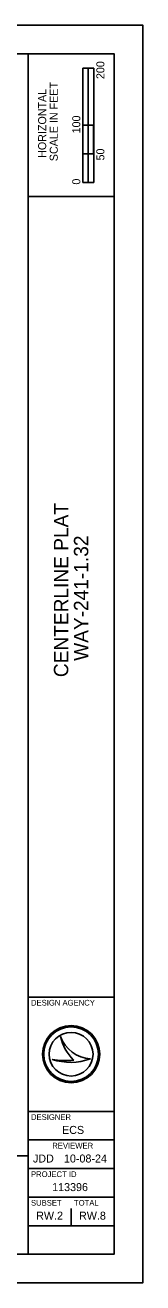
# Model space of a CAD drawing. Extents: x 2183298 to 2188248, y 369076 to 371276.
# Drawn here: x 2186493 to 2186698, y 369076 to 371276 of the extents above; entities that cross this region are included whole.
import ezdxf

# ---------------------------------------------------------------- set-up
doc = ezdxf.new("R2010")
doc.units = 0
for name, color, linetype in [('RD_X_RR_Cells', 7, 'Continuous'), ('SV_P_Mon_Cells_Set', 7, 'Continuous'), ('SV_X_Mon_Cells_Found', 7, 'Continuous'), ('SV_X_Shot_Marker', 7, 'Continuous')]:
    doc.layers.add(name, color=color, linetype=linetype)

msp = doc.modelspace()

# ---------------------------------------------------------------- linework, layer by layer
at = {"layer": 'RD_X_RR_Cells'}
for p, q in [((2186497.7, 369126.3), (2186497.7, 371226.3)), ((2186497.7, 370976.3), (2186647.7, 370976.3)), ((2186497.7, 369576.3), (2186647.7, 369576.3)), ((2186497.7, 369376.3), (2186647.7, 369376.3)), ((2186497.7, 369326.3), (2186647.7, 369326.3)), ((2186497.7, 369276.3), (2186647.7, 369276.3)), ((2186497.7, 369226.3), (2186647.7, 369226.3)), ((2186497.7, 369176.3), (2186647.7, 369176.3))]:
    msp.add_line(p, q, dxfattribs=at)
msp.add_lwpolyline([(2183447.7, 371226.3), (2186647.7, 371226.3), (2186647.7, 369126.3), (2183447.7, 369126.3)], close=True, dxfattribs=at)
at = {"layer": 'SV_P_Mon_Cells_Set'}
for p, q in [((2186593.3, 371001.3), (2186593.3, 371201.3)), ((2186612.1, 371201.3), (2186593.3, 371201.3)), ((2186593.3, 371101.3), (2186593.3, 371201.3)), ((2186593.3, 371201.3), (2186602.7, 371201.3)), ((2186602.7, 371201.3), (2186602.7, 371101.3)), ((2186602.7, 371201.3), (2186602.7, 371201.3)), ((2186612.1, 371201.3), (2186612.1, 371001.3)), ((2186602.7, 371101.3), (2186593.3, 371101.3)), ((2186612, 371101.3), (2186602.7, 371101.3)), ((2186602.7, 371101.3), (2186602.7, 371051.3)), ((2186612, 371051.3), (2186612, 371101.3)), ((2186602.7, 371051.3), (2186593.3, 371051.3)), ((2186593.3, 371051.3), (2186593.3, 371001.3)), ((2186602.7, 371051.3), (2186612, 371051.3)), ((2186602.7, 371001.3), (2186602.7, 371051.3)), ((2186612.1, 371001.3), (2186593.3, 371001.3)), ((2186593.3, 371001.3), (2186602.7, 371001.3)), ((2186554.4, 369507.3), (2186554.4, 369507.3)), ((2186572.7, 369476.3), (2186572.7, 369476.3)), ((2186606.4, 369468.1), (2186606.4, 369468.1)), ((2186539.4, 369467.3), (2186539.4, 369467.3)), ((2186572.7, 369176.3), (2186572.7, 369206.3))]:
    msp.add_line(p, q, dxfattribs=at)
for radius in [50, 47.7, 47.7, 38.2]:
    msp.add_circle((2186572.7, 369476.3), radius, dxfattribs=at)
for centre, radius, start, end in [((2186609.3, 369526.1), 58, 198.9257, 198.9319), ((2186632.3, 369523.3), 79.6, 191.6379, 191.6421), ((2186609.3, 369526.1), 58, 198.9319, 267.1657), ((2186632.3, 369523.3), 79.6, 191.6421, 226.0947), ((2186571.6, 369563.3), 101.3, 251.4576, 290.0832), ((2186562.5, 369591.7), 126.6, 259.4964, 259.4995), ((2186571.6, 369563.3), 101.3, 251.4527, 251.4576), ((2186562.5, 369591.7), 126.6, 259.4995, 276.6672)]:
    msp.add_arc(centre, radius, start, end, dxfattribs=at)
at = {"layer": 'SV_X_Mon_Cells_Found'}
msp.add_lwpolyline([(2183297.7, 369076.3), (2186697.7, 369076.3), (2186697.7, 371276.3), (2183297.7, 371276.3)], close=True, dxfattribs=at)
at = {"layer": 'SV_X_Shot_Marker'}
for p, q in [((2186160, 369298.7), (2186497.7, 369298.7)), ((2186497.7, 369298.7), (2186497.7, 369126.3))]:
    msp.add_line(p, q, dxfattribs=at)

# ---------------------------------------------------------------- texts
at = {"layer": 'SV_P_Mon_Cells_Set'}
for s, height, p in [('200', 14, (2186630.7, 371182)), ('HORIZONTAL', 14, (2186529.2, 371044.2)), ('SCALE IN FEET', 14, (2186549.4, 371038.4)), ('100', 14, (2186588.7, 371087)), ('50', 14, (2186630.7, 371039.6)), ('0', 14, (2186588.7, 370997.4)), ('CENTERLINE PLAT', 25, (2186567.7, 370135.8)), ('WAY-241-1.32', 25, (2186602.6, 370164.3))]:
    msp.add_text(s, height=height, rotation=90, dxfattribs=at).set_placement(p)
for s, height, p in [('DESIGN AGENCY', 10, (2186502.7, 369561.3)), ('DESIGNER', 10, (2186502.7, 369361.3)), ('ECS', 14, (2186556.9, 369336.8)), ('REVIEWER', 10, (2186539.8, 369311.3)), ('JDD', 14, (2186506.1, 369286.8)), ('10-08-24', 14, (2186560.2, 369286.8)), ('PROJECT ID', 10, (2186502.7, 369261.3)), ('113396', 14, (2186539.6, 369236.8)), ('SUBSET', 10, (2186502.7, 369211.3)), ('TOTAL', 10, (2186577.7, 369211.3)), ('RW.2', 14, (2186511.7, 369186.8)), ('RW.8', 14, (2186586.5, 369186.8))]:
    msp.add_text(s, height=height, dxfattribs=at).set_placement(p)

doc.saveas('drawing.dxf')
